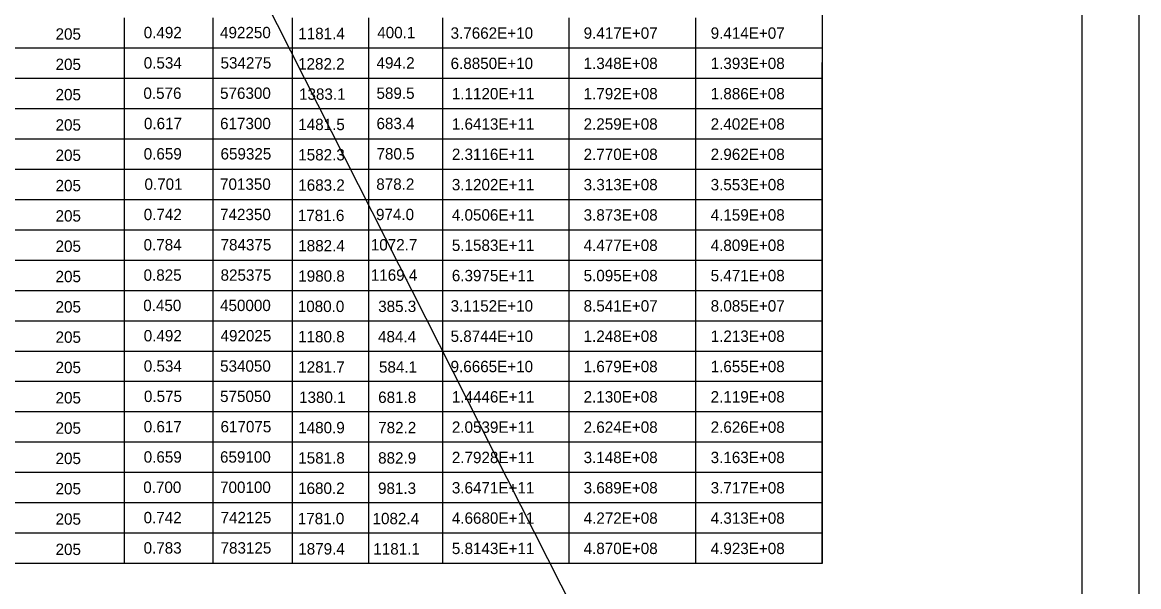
# Model space of a CAD drawing. Extents: x 635698 to 639877, y 296617 to 300175.
# Drawn here: x 637052.1 to 637346.5, y 298528.1 to 298677.1 of the extents above; entities that cross this region are included whole.
import ezdxf

# ---------------------------------------------------------------- set-up
doc = ezdxf.new("R2010")
doc.units = 0
for name, color, linetype in [('1', 7, 'Continuous'), ('2', 7, 'Continuous'), ('PLT-BNDY', 7, 'Continuous')]:
    doc.layers.add(name, color=color, linetype=linetype)

msp = doc.modelspace()

# ---------------------------------------------------------------- linework, layer by layer
at = {"layer": '1'}
msp.add_line((636360.88, 300174.81), (637328.96, 298262.27), dxfattribs=at)
at = {"layer": '2'}
for p, q in [((637331.45, 298861.76), (637331.45, 298297.76)), ((637262.96, 298851.84), (637262.96, 298534.25)), ((637078.96, 298678.25), (637078.96, 298606.25)), ((637102.34, 298678.25), (637102.34, 298606.25)), ((637123.21, 298678.25), (637123.21, 298606.25)), ((637143.34, 298678.25), (637143.34, 298606.25)), ((637162.84, 298678.25), (637162.84, 298606.25)), ((637196.21, 298678.25), (637196.21, 298606.25)), ((637229.59, 298678.25), (637229.59, 298606.25)), ((637262.96, 298670.25), (636768.84, 298670.25)), ((637262.96, 298576.99), (637262.96, 298666.49)), ((637262.96, 298662.25), (636768.84, 298662.25)), ((637262.96, 298654.25), (636768.84, 298654.25)), ((637262.96, 298646.25), (636768.84, 298646.25)), ((637262.96, 298638.25), (636768.84, 298638.25)), ((637262.96, 298630.25), (636768.84, 298630.25)), ((637262.96, 298622.25), (636768.84, 298622.25)), ((637262.96, 298614.25), (636768.84, 298614.25)), ((637262.96, 298606.25), (636768.84, 298606.25)), ((637262.96, 298606.25), (636768.84, 298606.25)), ((637262.96, 298606.25), (637078.96, 298606.25)), ((637078.96, 298606.25), (637078.96, 298534.25)), ((637102.34, 298606.25), (637102.34, 298534.25)), ((637123.21, 298606.25), (637123.21, 298534.25)), ((637143.34, 298606.25), (637143.34, 298534.25)), ((637162.84, 298606.25), (637162.84, 298534.25)), ((637196.21, 298606.25), (637196.21, 298534.25)), ((637229.59, 298606.25), (637229.59, 298534.25)), ((637262.96, 298534.25), (637262.96, 298606.25)), ((637262.96, 298598.25), (636768.84, 298598.25)), ((637262.96, 298590.25), (636768.84, 298590.25)), ((637262.96, 298582.25), (636768.84, 298582.25)), ((637262.96, 298574.25), (636768.84, 298574.25)), ((637262.96, 298566.25), (636768.84, 298566.25)), ((637262.96, 298558.25), (636768.84, 298558.25)), ((637262.96, 298550.25), (636768.84, 298550.25)), ((637262.96, 298542.25), (636768.84, 298542.25)), ((637262.96, 298534.25), (636554.2, 298534.25)), ((637262.96, 298534.25), (636768.84, 298534.25))]:
    msp.add_line(p, q, dxfattribs=at)
at = {"layer": 'PLT-BNDY'}
msp.add_lwpolyline([(636505.45, 298876.76), (637346.45, 298876.76), (637346.45, 298282.76), (636505.45, 298282.76)], close=True, dxfattribs=at)

# ---------------------------------------------------------------- texts
at = {"layer": '2'}
for s, p in [('205', (637060.84, 298672.5)), ('0.492', (637084.09, 298672.88)), ('492250', (637104.21, 298672.88)), ('1181.4', (637124.84, 298672.63)), ('400.1', (637145.67, 298672.88)), ('3.7662E+10', (637165.01, 298672.75)), ('9.417E+07', (637200.09, 298672.75)), ('9.414E+07', (637233.59, 298672.75)), ('205', (637060.84, 298664.5)), ('0.534', (637084.09, 298664.88)), ('534275', (637104.34, 298664.88)), ('1282.2', (637124.8, 298664.63)), ('494.2', (637145.48, 298664.88)), ('6.8850E+10', (637165.01, 298664.75)), ('1.348E+08', (637200.09, 298664.75)), ('1.393E+08', (637233.59, 298664.75)), ('205', (637060.84, 298656.5)), ('0.576', (637084.01, 298656.88)), ('576300', (637104.22, 298656.88)), ('1383.1', (637125.04, 298656.63)), ('589.5', (637145.47, 298656.88)), ('1.1120E+11', (637165.34, 298656.75)), ('1.792E+08', (637200.09, 298656.75)), ('1.886E+08', (637233.59, 298656.75)), ('205', (637060.84, 298648.5)), ('0.617', (637084.14, 298648.88)), ('617300', (637104.22, 298648.88)), ('1481.5', (637124.84, 298648.63)), ('683.4', (637145.47, 298648.88)), ('1.6413E+11', (637165.34, 298648.75)), ('2.259E+08', (637200.09, 298648.75)), ('2.402E+08', (637233.59, 298648.75)), ('0.659', (637084.08, 298640.88)), ('659325', (637104.34, 298640.88)), ('780.5', (637145.47, 298640.88)), ('2.3116E+11', (637165.34, 298640.75)), ('2.770E+08', (637200.09, 298640.75)), ('2.962E+08', (637233.59, 298640.75)), ('205', (637060.84, 298640.5)), ('1582.3', (637124.84, 298640.63)), ('205', (637060.84, 298632.5)), ('0.701', (637084.29, 298632.88)), ('701350', (637104.21, 298632.88)), ('1683.2', (637124.84, 298632.63)), ('878.2', (637145.41, 298632.88)), ('3.1202E+11', (637165.34, 298632.75)), ('3.313E+08', (637200.09, 298632.75)), ('3.553E+08', (637233.59, 298632.75)), ('205', (637060.84, 298624.5)), ('0.742', (637084.09, 298624.88)), ('742350', (637104.22, 298624.88)), ('1781.6', (637124.72, 298624.63)), ('974.0', (637145.34, 298624.88)), ('4.0506E+11', (637165.34, 298624.75)), ('3.873E+08', (637200.09, 298624.75)), ('4.159E+08', (637233.59, 298624.75)), ('205', (637060.84, 298616.5)), ('0.784', (637084.05, 298616.88)), ('784375', (637104.35, 298616.88)), ('1882.4', (637124.84, 298616.63)), ('1072.7', (637143.97, 298616.88)), ('5.1583E+11', (637165.34, 298616.75)), ('4.477E+08', (637200.09, 298616.75)), ('4.809E+08', (637233.59, 298616.75)), ('205', (637060.84, 298608.5)), ('0.825', (637084.05, 298608.88)), ('825375', (637104.35, 298608.88)), ('1980.8', (637124.84, 298608.63)), ('1169.4', (637143.97, 298608.88)), ('6.3975E+11', (637165.34, 298608.75)), ('5.095E+08', (637200.09, 298608.75)), ('5.471E+08', (637233.59, 298608.75)), ('205', (637060.84, 298600.5)), ('0.450', (637083.96, 298600.88)), ('450000', (637104.21, 298600.88)), ('1080.0', (637124.71, 298600.63)), ('385.3', (637145.91, 298600.63)), ('3.1152E+10', (637165.01, 298600.75)), ('8.541E+07', (637200.09, 298600.75)), ('8.085E+07', (637233.59, 298600.75)), ('205', (637060.84, 298592.5)), ('0.492', (637084.09, 298592.88)), ('492025', (637104.34, 298592.88)), ('1180.8', (637124.8, 298592.63)), ('484.4', (637145.87, 298592.63)), ('5.8744E+10', (637165.01, 298592.75)), ('1.248E+08', (637200.09, 298592.75)), ('1.213E+08', (637233.59, 298592.75)), ('0.534', (637084.1, 298584.88)), ('534050', (637104.22, 298584.88)), ('205', (637060.84, 298584.5)), ('1281.7', (637124.84, 298584.63)), ('584.1', (637146.12, 298584.63)), ('9.6665E+10', (637165.01, 298584.75)), ('1.679E+08', (637200.09, 298584.75)), ('1.655E+08', (637233.59, 298584.75)), ('205', (637060.84, 298576.5)), ('0.575', (637084.14, 298576.88)), ('575050', (637104.22, 298576.88)), ('1380.1', (637125.05, 298576.63)), ('681.8', (637145.91, 298576.63)), ('1.4446E+11', (637165.34, 298576.75)), ('2.130E+08', (637200.09, 298576.75)), ('2.119E+08', (637233.59, 298576.75)), ('205', (637060.84, 298568.5)), ('0.617', (637084.09, 298568.88)), ('617075', (637104.34, 298568.88)), ('1480.9', (637124.83, 298568.63)), ('782.2', (637145.91, 298568.63)), ('2.0539E+11', (637165.34, 298568.75)), ('2.624E+08', (637200.09, 298568.75)), ('2.626E+08', (637233.59, 298568.75)), ('205', (637060.84, 298560.5)), ('0.659', (637084.08, 298560.88)), ('659100', (637104.21, 298560.88)), ('1581.8', (637124.84, 298560.63)), ('882.9', (637145.9, 298560.63)), ('2.7928E+11', (637165.34, 298560.75)), ('3.148E+08', (637200.09, 298560.75)), ('3.163E+08', (637233.59, 298560.75)), ('205', (637060.84, 298552.5)), ('0.700', (637083.96, 298552.88)), ('700100', (637104.22, 298552.88)), ('1680.2', (637124.8, 298552.63)), ('981.3', (637145.87, 298552.63)), ('3.6471E+11', (637165.34, 298552.75)), ('3.689E+08', (637200.09, 298552.75)), ('3.717E+08', (637233.59, 298552.75)), ('205', (637060.84, 298544.5)), ('0.742', (637084.05, 298544.88)), ('742125', (637104.35, 298544.88)), ('1781.0', (637124.71, 298544.63)), ('1082.4', (637144.43, 298544.63)), ('4.6680E+11', (637165.34, 298544.75)), ('4.272E+08', (637200.1, 298544.75)), ('4.313E+08', (637233.59, 298544.75)), ('205', (637060.84, 298536.5)), ('0.783', (637084.05, 298536.88)), ('783125', (637104.35, 298536.88)), ('1879.4', (637124.84, 298536.63)), ('1181.1', (637144.63, 298536.63)), ('5.8143E+11', (637165.34, 298536.75)), ('4.870E+08', (637200.09, 298536.75)), ('4.923E+08', (637233.59, 298536.75))]:
    msp.add_text(s, height=3, dxfattribs=at).set_placement(p)

doc.saveas('drawing.dxf')
